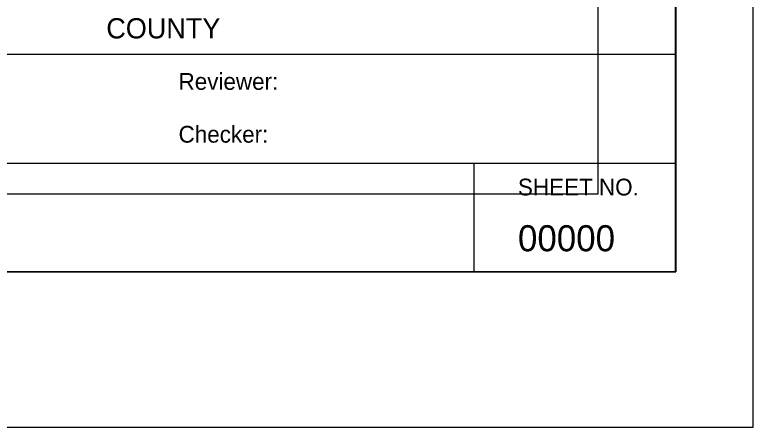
# Model space of a CAD drawing. Extents: x 0 to 1.42, y 0 to 0.92.
# Drawn here: x 1.2186 to 1.4167, y 0 to 0.1106 of the extents above; entities that cross this region are included whole.
import ezdxf

# ---------------------------------------------------------------- set-up
doc = ezdxf.new("R2010")
doc.units = 0
for name, color, linetype in [('#plot_layout', 7, 'Continuous'), ('#plot_shape', 7, 'Continuous'), ('P_ODOT_PLAN_Border', 7, 'Continuous'), ('P_ODOT_PLAN_General', 7, 'Continuous'), ('P_ODOT_PLAN_TBlock', 7, 'Continuous'), ('P_ODOT_PLAN_TBProjectInfo', 7, 'Continuous'), ('P_ODOT_PLAN_TBShtDwgNo', 7, 'Continuous')]:
    doc.layers.add(name, color=color, linetype=linetype)

msp = doc.modelspace()

# ---------------------------------------------------------------- linework, layer by layer
at = {"layer": '#plot_layout'}
msp.add_lwpolyline([(0.08333, 0.45832), (1.37503, 0.45832), (1.37503, 0.0625), (0.08333, 0.0625)], close=True, dxfattribs=at)
at = {"layer": '#plot_shape'}
msp.add_lwpolyline([(0, 0), (1.41667, 0), (1.41667, 0.91667), (0, 0.91667)], close=True, dxfattribs=at)
at = {"layer": 'P_ODOT_PLAN_Border'}
msp.add_lwpolyline([(0.0625, 0.04167), (1.39583, 0.04167), (1.39583, 0.875), (0.0625, 0.875)], close=True, dxfattribs=at)
at = {"layer": 'P_ODOT_PLAN_General'}
msp.add_lwpolyline([(1.39587, 0.04167), (0.88904, 0.04167), (0.88904, 0.22282), (1.39587, 0.22282)], close=True, dxfattribs=at)
at = {"layer": 'P_ODOT_PLAN_TBlock'}
for p, q in [((1.39587, 0.1), (1.12088, 0.1)), ((1.3417, 0.07083), (1.3417, 0.04167))]:
    msp.add_line(p, q, dxfattribs=at)
msp.add_lwpolyline([(0.95837, 0.04167), (1.39587, 0.04167), (1.39587, 0.21667), (0.95837, 0.21667)], close=True, dxfattribs=at)
msp.add_lwpolyline([(1.12088, 0.07083), (1.3417, 0.07083), (1.39587, 0.07083)], dxfattribs=at)

# ---------------------------------------------------------------- texts
for s, p in [('Reviewer:', (1.26254, 0.0905)), ('Checker:', (1.26254, 0.07633)), ('SHEET NO.', (1.35356, 0.06217))]:
    msp.add_text(s, height=0.0045, dxfattribs=at).set_placement(p)
at = {"layer": 'P_ODOT_PLAN_TBProjectInfo'}
msp.add_text('COUNTY', height=0.00542, dxfattribs=at).set_placement((1.24316, 0.10429))
at = {"layer": 'P_ODOT_PLAN_TBShtDwgNo'}
msp.add_text('00000', height=0.007, dxfattribs=at).set_placement((1.35357, 0.04719))

doc.saveas('drawing.dxf')
